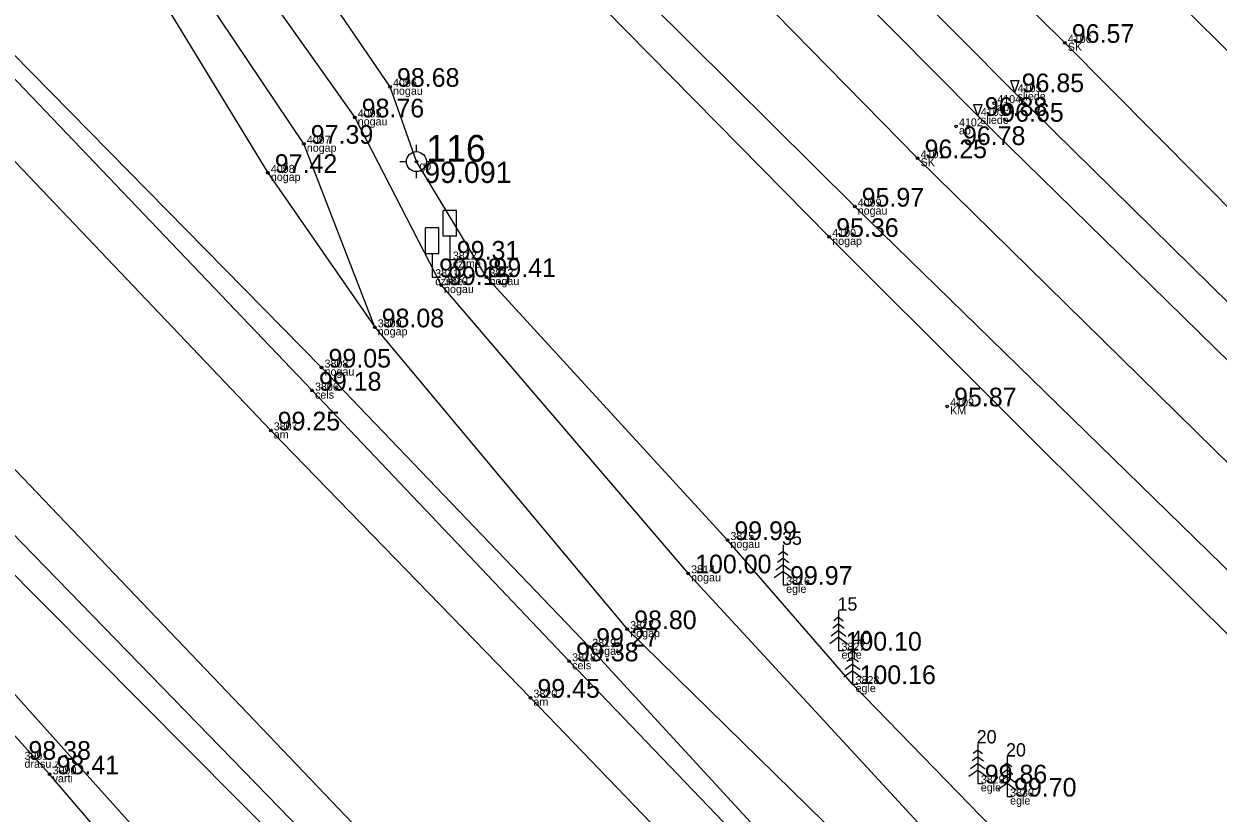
# Model space of a CAD drawing. Extents: x 614911 to 615803, y 262110 to 264311.
# Drawn here: x 615560.14 to 615604.92, y 264217 to 264246.6 of the extents above; entities that cross this region are included whole.
import ezdxf

# ---------------------------------------------------------------- set-up
doc = ezdxf.new("R2010")
doc.units = 0
for name, color, linetype in [('Level 1', 7, 'Continuous'), ('Level 16', 7, 'Continuous'), ('Level 19', 7, 'Continuous'), ('Level 31', 7, 'Continuous'), ('Level 37', 7, 'Continuous'), ('Level 53', 7, 'Continuous'), ('Level 54', 7, 'Continuous'), ('Level 57', 7, 'Continuous'), ('Level 58', 7, 'Continuous')]:
    doc.layers.add(name, color=color, linetype=linetype)

msp = doc.modelspace()

# ---------------------------------------------------------------- linework, layer by layer
at = {"layer": 'Level 1'}
for p, q in [((615588.611, 264226.813), (615588.435, 264226.685)), ((615588.611, 264227.063), (615588.611, 264225.563)), ((615588.611, 264226.813), (615588.785, 264226.685)), ((615588.611, 264226.313), (615588.333, 264226.109)), ((615588.611, 264226.563), (615588.395, 264226.405)), ((615588.611, 264226.563), (615588.827, 264226.405)), ((615588.611, 264226.313), (615588.889, 264226.109)), ((615588.611, 264226.063), (615588.279, 264225.819)), ((615588.611, 264226.063), (615588.945, 264225.819)), ((615588.611, 264225.563), (615588.811, 264225.563)), ((615590.689, 264224.595), (615590.689, 264223.095)), ((615590.689, 264224.095), (615590.473, 264223.937)), ((615590.689, 264224.345), (615590.513, 264224.217)), ((615590.689, 264224.345), (615590.863, 264224.217)), ((615590.689, 264224.095), (615590.905, 264223.937)), ((615590.689, 264223.595), (615590.357, 264223.351)), ((615590.689, 264223.845), (615590.411, 264223.641)), ((615590.689, 264223.845), (615590.967, 264223.641)), ((615590.689, 264223.595), (615591.023, 264223.351)), ((615591.216, 264223.341), (615591.216, 264221.841)), ((615590.689, 264223.095), (615590.889, 264223.095)), ((615591.216, 264222.841), (615591, 264222.683)), ((615591.216, 264223.091), (615591.04, 264222.963)), ((615591.216, 264223.091), (615591.39, 264222.963)), ((615591.216, 264222.841), (615591.432, 264222.683)), ((615591.216, 264222.341), (615590.884, 264222.097)), ((615591.216, 264222.591), (615590.938, 264222.387)), ((615591.216, 264222.591), (615591.494, 264222.387)), ((615591.216, 264222.341), (615591.55, 264222.097)), ((615591.216, 264221.841), (615591.416, 264221.841)), ((615595.911, 264219.616), (615595.911, 264218.116)), ((615595.911, 264219.116), (615595.695, 264218.958)), ((615595.911, 264219.366), (615595.735, 264219.238)), ((615595.911, 264219.366), (615596.085, 264219.238)), ((615595.911, 264219.116), (615596.127, 264218.958)), ((615597.01, 264219.124), (615597.01, 264217.624)), ((615595.911, 264218.866), (615595.633, 264218.662)), ((615595.911, 264218.866), (615596.189, 264218.662)), ((615597.01, 264218.874), (615596.834, 264218.746)), ((615597.01, 264218.874), (615597.184, 264218.746)), ((615595.911, 264218.616), (615595.579, 264218.372)), ((615595.911, 264218.616), (615596.245, 264218.372)), ((615597.01, 264218.374), (615596.732, 264218.17)), ((615597.01, 264218.624), (615596.794, 264218.466)), ((615597.01, 264218.624), (615597.226, 264218.466)), ((615597.01, 264218.374), (615597.288, 264218.17)), ((615595.911, 264218.116), (615596.111, 264218.116)), ((615597.01, 264218.124), (615596.678, 264217.88)), ((615597.01, 264218.124), (615597.344, 264217.88)), ((615597.01, 264217.624), (615597.21, 264217.624))]:
    msp.add_line(p, q, dxfattribs=at)
at = {"layer": 'Level 16'}
for p, q in [((615576.361, 264239.605), (615575.861, 264239.605)), ((615575.861, 264238.636), (615575.861, 264239.605)), ((615576.361, 264238.636), (615576.361, 264239.605)), ((615575.698, 264238.946), (615575.198, 264238.946)), ((615575.198, 264237.977), (615575.198, 264238.946)), ((615575.698, 264237.977), (615575.698, 264238.946)), ((615576.361, 264238.636), (615575.861, 264238.636)), ((615576.115, 264238.636), (615576.115, 264237.758)), ((615575.698, 264237.977), (615575.198, 264237.977)), ((615575.452, 264237.977), (615575.452, 264237.099)), ((615576.115, 264237.758), (615576.43, 264237.758)), ((615575.452, 264237.099), (615575.767, 264237.099))]:
    msp.add_line(p, q, dxfattribs=at)
at = {"layer": 'Level 19'}
for p, q in [((615574.859, 264241.806), (615574.859, 264242.056)), ((615574.234, 264241.431), (615574.484, 264241.431)), ((615574.859, 264240.806), (615574.859, 264241.056)), ((615575.234, 264241.431), (615575.484, 264241.431))]:
    msp.add_line(p, q, dxfattribs=at)
for radius in [0.375, 0.05]:
    msp.add_circle((615574.859, 264241.431), radius, dxfattribs=at)
at = {"layer": 'Level 31'}
for points in [[(615762.569, 264108.432), (615743.376, 264122.276), (615723.221, 264138.687), (615705.147, 264153.725), (615674.877, 264181.955), (615656.951, 264197.747), (615637.976, 264214.014), (615619.221, 264231.816), (615602.006, 264248.823), (615581.186, 264269.584), (615564.897, 264285.757), (615549.808, 264302.584)], [(615540.752, 264293.153), (615554.871, 264276.489), (615571.152, 264259.742), (615591.296, 264239.745), (615608.637, 264222.837), (615628.706, 264203.767), (615646.768, 264187.421), (615664.713, 264171.246), (615679.702, 264157.791), (615695.65, 264144.718), (615713.644, 264129.017), (615734.176, 264112.026), (615754.636, 264096.634)], [(615753.478, 264095.562), (615733.7, 264111.337), (615712.842, 264127.996), (615696.82, 264142.035), (615679.383, 264156.731), (615663.464, 264170.411), (615645.861, 264186.034), (615627.735, 264202.684), (615607.548, 264221.434), (615590.341, 264238.61), (615571.816, 264257.419), (615555.77, 264271.235), (615553.667, 264275.682), (615546.609, 264281.236), (615539.858, 264291.16)], [(615744.764, 264081.359), (615732.887, 264089.943), (615715.889, 264102.764), (615694.682, 264119.208), (615676.974, 264133.244), (615650.72, 264155.552), (615629.606, 264174.135), (615612.305, 264190.628), (615596.307, 264206.969), (615581.341, 264223.238), (615571.304, 264233.709), (615558.243, 264246.987), (615542.242, 264265.322), (615529.994, 264284)], [(615545.518, 264280.427), (615550.15, 264273.196), (615552.037, 264269.332), (615556.115, 264261.124), (615563.231, 264250.963), (615569.29, 264241.01), (615573.297, 264235.218), (615570.638, 264242.102), (615564.337, 264251.48), (615558.367, 264261.002), (615553.059, 264269.384), (615553.588, 264271.571), (615555.77, 264271.235)], [(615664.052, 264155.366), (615649.085, 264167.868), (615634.68, 264180.06), (615617.294, 264196.873), (615601.293, 264211.473), (615591.216, 264221.841), (615586.523, 264227.242), (615577.49, 264237.102), (615574.859, 264241.431), (615573.871, 264244.238), (615567.337, 264253.806), (615559.696, 264264.829), (615554.808, 264269.231), (615558.127, 264264.081), (615565.889, 264252.476), (615572.548, 264243.09), (615575.785, 264236.804), (615585.051, 264225.993), (615599.922, 264209.867), (615615.215, 264194.443), (615632.683, 264177.591), (615652.699, 264158.282), (615678.791, 264135.883)], [(615573.297, 264235.218), (615582.765, 264223.901), (615598.169, 264208.795), (615613.95, 264192.439), (615631.402, 264176.068), (615651.799, 264157.165), (615678.305, 264134.819), (615695.98, 264121.225), (615717.243, 264104.936), (615734.373, 264091.846), (615746.465, 264082.76)], [(615586.835, 264187.816), (615584.099, 264192.736), (615568, 264210.39), (615561.107, 264218.459), (615550.946, 264229.693), (615551.547, 264230.882), (615553.756, 264232.003), (615571.747, 264213.885), (615585.706, 264197.812), (615588.191, 264195.108), (615589.392, 264186.838), (615592.266, 264179.078), (615598.78, 264165.455), (615601.089, 264155.836), (615603.013, 264133.671), (615602.976, 264130.78), (615600.849, 264126.828)], [(615600.849, 264126.828), (615601.549, 264130.958), (615601.685, 264134.866), (615599.671, 264152.885), (615597.708, 264164.507), (615594.779, 264169.798), (615590.966, 264178.56), (615588.015, 264186.729), (615586.483, 264191.829), (615585.159, 264194.038), (615568.866, 264211.337), (615556.688, 264224.915), (615551.999, 264230.205)]]:
    msp.add_lwpolyline(points, dxfattribs=at)
at = {"layer": 'Level 37'}
for points in [[(615761.079, 264103.167), (615740.608, 264118.87), (615720.064, 264135.41), (615702.164, 264150.358), (615683.412, 264166.162), (615670.618, 264177.317), (615652.713, 264193.863), (615634.786, 264210.699), (615620.941, 264223.967), (615615.966, 264228.972), (615599.176, 264245.886), (615578.012, 264266.798), (615562.423, 264283.045), (615547.324, 264299.857)], [(615759.565, 264101.106), (615739.143, 264117.266), (615718.667, 264134.033), (615701.498, 264148.445), (615682.756, 264164.518), (615669.543, 264176.126), (615651.347, 264192.511), (615633.272, 264209.191), (615614.204, 264227.4), (615597.285, 264244.019), (615576.358, 264265.082), (615560.633, 264281.446), (615545.346, 264297.738)], [(615544.24, 264296.658), (615559.48, 264280.438), (615575.312, 264263.924), (615595.914, 264243.146), (615613.083, 264226.335), (615632.332, 264207.923), (615650.408, 264191.231), (615668.49, 264174.989), (615684.179, 264161.185), (615702.875, 264145.178), (615717.148, 264133.231), (615738.189, 264116.022), (615758.45, 264099.985)], [(615540.752, 264293.153), (615550.108, 264282.114), (615552.773, 264283.226), (615557.41, 264278.457), (615573.64, 264261.965), (615593.655, 264241.56), (615611.026, 264224.494), (615630.543, 264205.827), (615648.416, 264189.194), (615666.454, 264173.12), (615670.636, 264169.646), (615672.409, 264164.575), (615679.702, 264157.791), (615684.212, 264153.509), (615692.685, 264150.342), (615697.341, 264145.636), (615715.517, 264131.224), (615736.783, 264114.465), (615756.444, 264098.349)], [(615526.871, 264279.709), (615557.508, 264246.916), (615570.946, 264232.844), (615580.588, 264222.695), (615595.945, 264206.676), (615612.011, 264190.126), (615629.214, 264173.64), (615650.344, 264154.99), (615676.59, 264132.802), (615694.345, 264118.703), (615715.543, 264102.359), (615732.654, 264089.574), (615744.576, 264080.858)], [(615743.178, 264079.076), (615731.345, 264087.792), (615714.316, 264100.575), (615693.008, 264116.957), (615675.219, 264131.222), (615649.561, 264152.667), (615627.765, 264171.974), (615611.182, 264188.292), (615594.351, 264205.525), (615579.137, 264221.33), (615569.398, 264231.353), (615556.134, 264245.272), (615540.03, 264262.148), (615525.148, 264277.969)], [(615557.255, 264165.996), (615560.766, 264162.719), (615577.593, 264147.263), (615588.494, 264136.267), (615599.506, 264126.302), (615604.516, 264126.922), (615608.515, 264131.923), (615605.689, 264157.864), (615604.187, 264174.742), (615600.319, 264185.074), (615597.633, 264190.544), (615588.228, 264200.318), (615573, 264216.061), (615549.842, 264240.316), (615534.253, 264256.654), (615518.861, 264272.941)], [(615517.733, 264271.939), (615532.797, 264255.433), (615548.294, 264239.24), (615571.879, 264214.984), (615586.806, 264199.076), (615593.682, 264192.665), (615600.319, 264185.074)]]:
    msp.add_lwpolyline(points, dxfattribs=at)
at = {"layer": 'Level 57'}
for centre in [(615599.176, 264245.886), (615573.871, 264244.238), (615596.53, 264243.627), (615572.548, 264243.09), (615595.094, 264242.754), (615570.638, 264242.102), (615593.655, 264241.56), (615569.29, 264241.01), (615591.296, 264239.745), (615590.341, 264238.61), (615577.49, 264237.102), (615575.785, 264236.804), (615573.297, 264235.218), (615571.304, 264233.709), (615570.946, 264232.844), (615594.763, 264232.254), (615569.398, 264231.353), (615586.523, 264227.242), (615585.051, 264225.993), (615582.765, 264223.901), (615581.341, 264223.238), (615580.588, 264222.695), (615579.137, 264221.33), (615561.107, 264218.459)]:
    msp.add_circle(centre, 0.05, dxfattribs=at)
at = {"layer": 'Level 58'}
for points in [[(615597.146, 264244.469), (615597.446, 264244.469), (615597.296, 264244.036)], [(615595.764, 264243.579), (615596.064, 264243.579), (615595.914, 264243.146)]]:
    msp.add_lwpolyline(points, close=True, dxfattribs=at)
for centre in [(615599.176, 264245.886), (615573.871, 264244.238), (615596.53, 264243.627), (615572.548, 264243.09), (615595.094, 264242.754), (615570.638, 264242.102), (615593.655, 264241.56), (615569.29, 264241.01), (615591.296, 264239.745), (615590.341, 264238.61), (615577.49, 264237.102), (615575.785, 264236.804), (615573.297, 264235.218), (615571.304, 264233.709), (615570.946, 264232.844), (615594.763, 264232.254), (615569.398, 264231.353), (615586.523, 264227.242), (615585.051, 264225.993), (615582.765, 264223.901), (615581.341, 264223.238), (615580.588, 264222.695), (615579.137, 264221.33), (615561.107, 264218.459)]:
    msp.add_circle(centre, 0.05, dxfattribs=at)

# ---------------------------------------------------------------- texts
at = {"layer": 'Level 1'}
for s, p in [(' 35', (615588.386, 264227.063)), (' 15', (615590.464, 264224.595)), (' 40', (615590.991, 264223.341)), (' 20', (615595.686, 264219.616)), (' 20', (615596.785, 264219.124))]:
    msp.add_text(s, height=0.5, dxfattribs=at).set_placement(p)
at = {"layer": 'Level 19'}
for s, height, p in [(' 116', 1, (615574.859, 264241.431)), (' 99.091', 0.8, (615574.859, 264240.631))]:
    msp.add_text(s, height=height, dxfattribs=at).set_placement(p)
at = {"layer": 'Level 53'}
for s, p in [(' SK', (615599.176, 264245.586)), (' nogau', (615573.871, 264243.938)), (' sliede', (615597.296, 264243.736)), (' ap', (615596.53, 264243.327)), (' nogau', (615572.548, 264242.79)), (' sliede', (615595.914, 264242.846)), (' ap', (615595.094, 264242.454)), (' nogap', (615570.638, 264241.802)), (' SK', (615593.655, 264241.26)), (' gp', (615574.859, 264241.131)), (' nogap', (615569.29, 264240.71)), (' nogau', (615591.296, 264239.445)), (' nogap', (615590.341, 264238.31)), (' czime', (615576.115, 264237.458)), (' czime', (615575.452, 264236.799)), (' nogau', (615577.49, 264236.802)), (' nogau', (615575.785, 264236.504)), (' nogap', (615573.297, 264234.918)), (' nogau', (615571.304, 264233.409)), (' cels', (615570.946, 264232.544)), (' KM', (615594.763, 264231.954)), (' am', (615569.398, 264231.053)), (' nogau', (615586.523, 264226.942)), (' nogau', (615585.051, 264225.693)), (' egle', (615588.611, 264225.263)), (' nogap', (615582.765, 264223.601)), (' nogau', (615581.341, 264222.938)), (' cels', (615580.588, 264222.395)), (' egle', (615590.689, 264222.795)), (' egle', (615591.216, 264221.541)), (' am', (615579.137, 264221.03)), (' drasu.z', (615560.052, 264218.703)), (' varti', (615561.107, 264218.159)), (' egle', (615595.911, 264217.816)), (' egle', (615597.01, 264217.324))]:
    msp.add_text(s, height=0.3, dxfattribs=at).set_placement(p)
at = {"layer": 'Level 54'}
for s, p in [(' 4106', (615599.176, 264245.886)), (' 4096', (615573.871, 264244.238)), (' 4105', (615597.296, 264244.036)), (' 4104', (615596.53, 264243.627)), (' 4095', (615572.548, 264243.09)), (' 4103', (615595.914, 264243.146)), (' 4102', (615595.094, 264242.754)), (' 4097', (615570.638, 264242.102)), (' 4101', (615593.655, 264241.56)), (' 4098', (615569.29, 264241.01)), (' 4099', (615591.296, 264239.745)), (' 4100', (615590.341, 264238.61)), (' 3812', (615576.115, 264237.758)), (' 3811', (615575.452, 264237.099)), (' 3810', (615575.785, 264236.804)), (' 3813', (615577.49, 264237.102)), (' 3809', (615573.297, 264235.218)), (' 3808', (615571.304, 264233.709)), (' 3806', (615570.946, 264232.844)), (' 4109', (615594.763, 264232.254)), (' 3807', (615569.398, 264231.353)), (' 3815', (615586.523, 264227.242)), (' 3814', (615585.051, 264225.993)), (' 3816', (615588.611, 264225.563)), (' 3817', (615582.765, 264223.901)), (' 3819', (615581.341, 264223.238)), (' 3827', (615590.689, 264223.095)), (' 3818', (615580.588, 264222.695)), (' 3828', (615591.216, 264221.841)), (' 3820', (615579.137, 264221.33)), (' 3991', (615560.052, 264219.003)), (' 3990', (615561.107, 264218.459)), (' 3829', (615595.911, 264218.116)), (' 3830', (615597.01, 264217.624))]:
    msp.add_text(s, height=0.3, dxfattribs=at).set_placement(p)
at = {"layer": 'Level 58'}
for s, p in [(' 96.57', (615599.176, 264245.886)), (' 98.68', (615573.871, 264244.238)), (' 96.85', (615597.296, 264244.036)), (' 98.76', (615572.548, 264243.09)), (' 96.88', (615595.914, 264243.146)), (' 96.65', (615596.53, 264242.927)), (' 97.39', (615570.638, 264242.102)), (' 96.78', (615595.094, 264242.054)), (' 96.25', (615593.655, 264241.56)), (' 97.42', (615569.29, 264241.01)), (' 95.97', (615591.296, 264239.745)), (' 95.36', (615590.341, 264238.61)), (' 99.31', (615576.115, 264237.758)), (' 99.08', (615575.452, 264237.099)), (' 99.15', (615575.785, 264236.804)), (' 99.41', (615577.49, 264237.102)), (' 98.08', (615573.297, 264235.218)), (' 99.05', (615571.304, 264233.709)), (' 99.18', (615570.946, 264232.844)), (' 95.87', (615594.763, 264232.254)), (' 99.25', (615569.398, 264231.353)), (' 99.99', (615586.523, 264227.242)), (' 100.00', (615585.051, 264225.993)), (' 99.97', (615588.611, 264225.563)), (' 98.80', (615582.765, 264223.901)), (' 99.27', (615581.341, 264223.238)), (' 100.10', (615590.689, 264223.095)), (' 99.38', (615580.588, 264222.695)), (' 100.16', (615591.216, 264221.841)), (' 99.45', (615579.137, 264221.33)), (' 98.38', (615560.052, 264219.003)), (' 98.41', (615561.107, 264218.459)), (' 99.86', (615595.911, 264218.116)), (' 99.70', (615597.01, 264217.624))]:
    msp.add_text(s, height=0.7, dxfattribs=at).set_placement(p)

doc.saveas('drawing.dxf')
